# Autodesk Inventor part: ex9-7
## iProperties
Shininess: 64.0
Length Units: 11272
Angle Units: 11279
Time Units: 11290
Mass Units: 11286
Length Display Precision: 3
Angle Display Precision: 2
Compacted: True
Part Number: ex9-7
Document SubType Name: Sheet Metal
Created: 2002-11
Designer: Elise Moss
Density: 0.0
Volumn: 0.0
Area: 0.0
PropertySet Name: Model Information
Control State: 0
Master: False
Checked Out: False
Author: Elise Moss
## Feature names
1. Plate1
2. Bend1
3. Plate2
4. Bend2
5. Cut1
